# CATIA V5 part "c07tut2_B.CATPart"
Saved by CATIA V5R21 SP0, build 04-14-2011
Part number: Part1
Bounding box of the stored display mesh (mm): x 0 to 32, y -32 to 32, z -15 to 36
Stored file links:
  D:\CATIA V5R21 E-RESOURCES\CATIA-V5R21\catia-v5r21-prt\c07-catia-v5r20-prt\c07-catia-v5r21-tut-2_B.CATPart
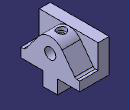
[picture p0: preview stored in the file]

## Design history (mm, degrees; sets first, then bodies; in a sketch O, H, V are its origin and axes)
Body1 (main body)
  Sketch1 on zx-plane, origin (0, 0, 0), H (-1, 0, 0), V (0, 0, 1)
    line L1 (0, 0) -> (0, 36)
    line L2 (0, 36) -> (-12, 36)
    line L3 (-12, 36) -> (-12, 10)
    line L4 (-12, 10) -> (-32, 10)
    line L5 (-32, 10) -> (-32, 0)
    point P5 (-32, 0)
    line L6 (-32, 0) -> (0, 0)
    length L1 = 36
    length L2 = 12
    length L5 = 10
    length L6 = 32
    vertical: L1 V, L3 V, L5 V
    horizontal: L2 H, L4 H, L6 H
    coincidence: P5 H
  Pad1: profile Sketch1, direction (0, 1, 0), length 32, mirrored extent
  Sketch2 on face of Pad1 from Sketch1.L5, origin (32, 0, 0), H (0, 1, 0), V (0, 0, 1)
    line L1 (0, 10) -> (27.5, 10)
    point P1 (0, 10)
    point P2 (27.5, 10)
    line L2 (27.5, 10) -> (12.8, 29.6)
    point P3 (12.8, 29.6)
    reference projected line E1 (-32, 10) -> (32, 10) from edge [face of Pad1 from Sketch1.L5 | face of Pad1 from Sketch1.L4]
    point P4 (-27.5, 10)
    point P5 (0, 10)
    line L3 (0, 10) -> (-27.5, 10)
    point P6 (-12.8, 29.6)
    line L4 (-27.5, 10) -> (-12.8, 29.6)
    arc A1 centre (0, 20) radius 16 from (12.8, 29.6) to (-12.8, 29.6) ccw
    reference projected line E2 (-32, 36) -> (32, 36) from edge [face of Pad1 from Sketch1.L3 | face of Pad1 from Sketch1.L2]
    radius A1 = 16
    distance P4 P2 = 55
    coincidence: P1 V, L1 E1, P1 P5
    horizontal: L1 H
    symmetry: P2 P4 V, P1 P5 V, L1 L3 V, P3 P6 V, L2 L4 V
    tangency: A1 L2, A1 E2
  Pad2: profile Sketch2, direction (1, 0, 0), up to the existing solid (limit type 2)
  Sketch3 on face of Pad2, origin (32, 0, 0), H (0, 1, 0), V (0, 0, 1)
    point P1 (-8, 0)
    line L1 (-8, 0) -> (8, 0)
    line L2 (8, 0) -> (8, -15)
    line L3 (8, -15) -> (-8, -15)
    line L4 (-8, -15) -> (-8, 0)
    length L3 = 16
    length L2 = 15
    distance L4 V = 8
    coincidence: P1 H
    horizontal: L1 H, L3 H
    vertical: L2 V, L4 V
  Pad3: profile Sketch3, direction (1, 0, 0), up to face of Pad1 from Sketch1.L1
  Sketch4 on zx-plane, origin (0, 0, 0), H (-1, 0, 0), V (0, 0, 1)
    point P1 (-20, 36)
    reference projected line E1 (0, 36) -> (-10, 36) from edge [face of Pad1 from Sketch1.L2 | end face of Pad1]
    distance P1 V = 20
    coincidence: P1 E1
  Sketch5 on {plane type Tangent, Support face of Pad2 from Sketch2.A1, RefPoint Sketch4.P1}, origin (20, 0, 36), H (1, 0, 0), V (0, -1, 0)
    point P1 (0, 0)
    reference projected point E1 (0, 0) from Sketch4.P1
    coincidence: E1 P1
  Hole1: placed by Sketch5, at (20, 0, 36) direction (0, 0, -1), diameter 6, depth 16, counterbore diameter 10, counterbore depth 4
  Fillet1: radius 3, on edge [face of Pad1 from Sketch1.L4 | face of Pad2 from Sketch2.L2]; edge [face of Pad2 from Sketch2.L4 | face of Pad1 from Sketch1.L4]
  Sketch6 on face of Pad3 from Sketch3.L3, origin (11.5351, 1.2048, -15), H (1, 0, 0), V (0, -1, 0)
    point P1 (-3.5351, 1.2048)
    reference projected line E1 (-11.5351, -6.7952) -> (-11.5351, 9.2048) from edge [face of Pad3 from Sketch3.L3 | end face of Pad3]
    reference projected line E2 (20.4649, -6.7952) -> (-11.5351, -6.7952) from edge [face of Pad3 from Sketch3.L3 | face of Pad3 from Sketch3.L2]
    distance P1 E1 = 8
    distance E2 P1 = 8
  Hole2: placed by Sketch6, at (8, 0, -15) direction (0, 0, 1), diameter 6, depth 16, V-bottom angle 120
  Sketch7 on face of Pad3 from Sketch3.L3, origin (26.6528, -0.5857, -15), H (1, 0, 0), V (0, -1, 0)
    point P1 (-2.6528, 0)
    reference projected line E1 (5.3472, -8.5857) -> (-26.6528, -8.5857) from edge [face of Pad3 from Sketch3.L3 | face of Pad3 from Sketch3.L2]
    reference projected point E2 (-18.6528, -0.5857) from edge
    distance E1 H = 8
    distance E2 P1 H = 16
  Hole3: placed by Sketch7, at (24, -0.5857, -15) direction (0, 0, 1), diameter 6, depth 16, V-bottom angle 120
  Sketch8 on face of Pad2, origin (32, -6.1541, 20.7645), H (0, 1, 0), V (0, 0, 1)
    point P1 (6.1541, -0.7645)
    reference projected arc E1 centre (6.1541, -0.7645) radius 16 from (18.9541, 8.8355) to (-6.6459, 8.8355) ccw from edge [face of Pad2 from Sketch2.A1 | start face of Pad2]
    concentricity: P1 E1
  Hole4: placed by Sketch8, at (32, 0, 20) direction (-1, 0, 0), diameter 12, depth 24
